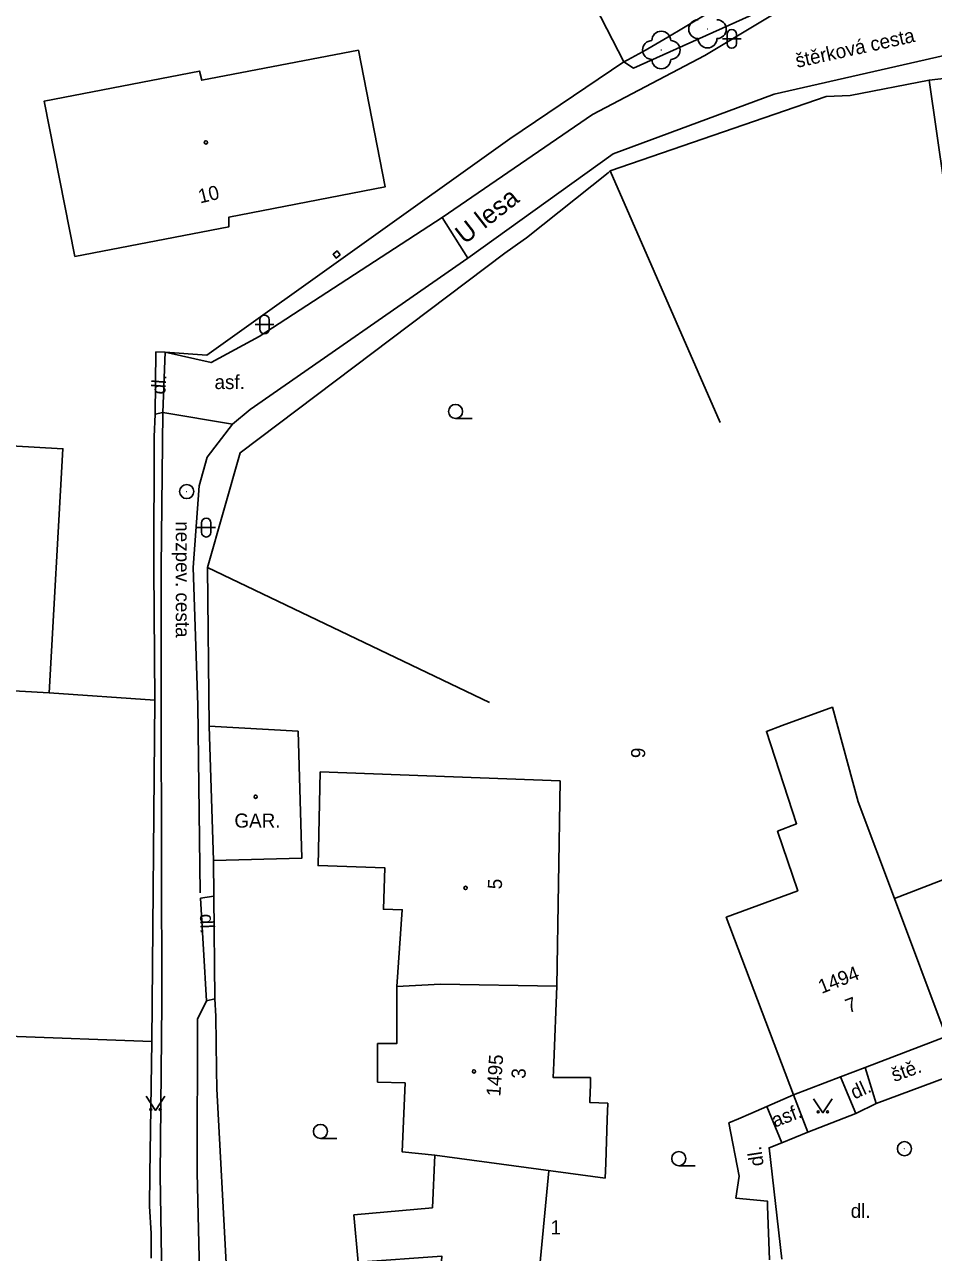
# Model space of a CAD drawing. Extents: x -584400 to -581602, y -1210894 to -1208793.
# Drawn here: x -583273.3 to -583224.9, y -1209541.9 to -1209476.6 of the extents above; entities that cross this region are included whole.
import ezdxf

# ---------------------------------------------------------------- set-up
doc = ezdxf.new("R2010")
doc.units = 0
for name, color, linetype in [('BUDOVY_MĚŘ', 7, 'Continuous'), ('BUDOVY_NEMĚŘ', 7, 'Continuous'), ('MAP_ZN_BP', 7, 'Continuous'), ('NÁZVY_ULIC_TOK_SMĚR', 7, 'Continuous'), ('OBVOD_PILÍŘE', 7, 'Continuous'), ('POMOC_POPIS', 7, 'Continuous'), ('ROZHRANÍ_PLOCH', 7, 'Continuous'), ('ZELEŇ', 7, 'Continuous'), ('ZN_BUDOV', 7, 'Continuous'), ('ZN_DOPLŇKOVÉ', 7, 'Continuous'), ('ZN_KULTUR', 7, 'Continuous'), ('Č_POPIS_EVID', 7, 'Continuous'), ('Č_POPIS_ORIENT', 7, 'Continuous')]:
    doc.layers.add(name, color=color, linetype=linetype)

msp = doc.modelspace()

# ---------------------------------------------------------------- linework, layer by layer
at = {"layer": 'BUDOVY_MĚŘ'}
for points in [[(-583270.59, -1209488.95), (-583262.4, -1209487.38), (-583262.39, -1209486.86), (-583254.08, -1209485.25), (-583255.49, -1209477.98)], [(-583225.12, -1209479.58), (-583224.33, -1209485.13), (-583221.4, -1209484.79), (-583222.19, -1209479.24), (-583225.12, -1209479.58)], [(-583281.65, -1209498.59), (-583271.23, -1209499.18), (-583271.96, -1209512.17), (-583282.38, -1209511.58), (-583281.65, -1209498.59)], [(-583258.7, -1209514.2), (-583263.44, -1209513.95), (-583263.22, -1209521.09), (-583258.52, -1209520.97), (-583258.7, -1209514.2)], [(-583244.76, -1209516.85), (-583257.54, -1209516.38)], [(-583251.14, -1209527.66), (-583253.46, -1209527.79)], [(-583242.36, -1209537.99), (-583242.33, -1209537.19), (-583242.26, -1209534.87), (-583242.23, -1209534), (-583243.18, -1209533.97), (-583243.18, -1209533.87), (-583243.15, -1209533.01), (-583243.15, -1209532.64), (-583244.78, -1209532.64), (-583245.13, -1209532.64), (-583245.1, -1209531.86), (-583244.94, -1209527.78), (-583251.14, -1209527.66)], [(-583254.48, -1209530.83), (-583253.46, -1209530.83), (-583253.46, -1209527.79)], [(-583251.55, -1209539.57), (-583251.44, -1209536.77), (-583253.18, -1209536.58), (-583253.02, -1209532.92), (-583254.48, -1209532.88), (-583254.48, -1209530.83)], [(-583232.34, -1209533.55), (-583229.85, -1209532.6), (-583228.53, -1209532.1), (-583224.22, -1209530.45)], [(-583242.36, -1209537.99), (-583251.44, -1209536.77)], [(-583255.74, -1209539.94), (-583251.55, -1209539.57)], [(-583251.98, -1209555.22), (-583251.06, -1209542.14), (-583255.52, -1209542.45), (-583255.74, -1209539.94)]]:
    msp.add_lwpolyline(points, dxfattribs=at)
at = {"layer": 'BUDOVY_NEMĚŘ'}
for points in [[(-583255.49, -1209477.98), (-583263.84, -1209479.58), (-583263.96, -1209479.09), (-583272.22, -1209480.69), (-583270.59, -1209488.95)], [(-583226.96, -1209523.11), (-583218.62, -1209519.89), (-583222.5, -1209508.4), (-583223.55, -1209501.49), (-583218.76, -1209500.73), (-583217.77, -1209507.6), (-583217.68, -1209509.16), (-583217.59, -1209510.64), (-583211.83, -1209525.68)], [(-583232.34, -1209533.55), (-583235.92, -1209524.11), (-583232.12, -1209522.7), (-583233.19, -1209519.53), (-583232.18, -1209519.13), (-583233.79, -1209514.22), (-583232.95, -1209513.91), (-583230.27, -1209512.94), (-583228.9, -1209517.96), (-583226.96, -1209523.11), (-583224.22, -1209530.45)], [(-583253.46, -1209527.79), (-583253.17, -1209523.71), (-583254.17, -1209523.68), (-583254.09, -1209521.48), (-583257.65, -1209521.36), (-583257.54, -1209516.38)], [(-583244.76, -1209516.85), (-583244.94, -1209527.78)], [(-583251.98, -1209555.22), (-583247.08, -1209555.68), (-583245.37, -1209537.59)]]:
    msp.add_lwpolyline(points, dxfattribs=at)
at = {"layer": 'MAP_ZN_BP'}
for centre, radius in [((-583264.64, -1209501.461), 0.375), ((-583264.64, -1209501.461), 0.0005), ((-583226.44, -1209536.421), 0.375), ((-583226.44, -1209536.421), 0.0005)]:
    msp.add_circle(centre, radius, dxfattribs=at)
at = {"layer": 'OBVOD_PILÍŘE'}
msp.add_lwpolyline([(-583256.47, -1209488.86), (-583256.64, -1209488.66), (-583256.85, -1209488.84), (-583256.68, -1209489.04), (-583256.47, -1209488.86)], dxfattribs=at)
at = {"layer": 'ROZHRANÍ_PLOCH'}
for points in [[(-583226.81, -1209472.03), (-583231.1, -1209474.67), (-583231.17, -1209474.5), (-583233.01, -1209475.41), (-583233.1, -1209475.23), (-583233.58, -1209475.47), (-583233.48, -1209475.62), (-583240.86, -1209478.94), (-583241.37, -1209478.6)], [(-583243.05, -1209481.4), (-583237.07, -1209478.27), (-583231.1, -1209474.67)], [(-583213.29, -1209477.22), (-583222.38, -1209477.82), (-583233.38, -1209480.32), (-583241.95, -1209483.5), (-583249.68, -1209489.04)], [(-583243.05, -1209481.4), (-583251.04, -1209486.89)], [(-583249.68, -1209489.04), (-583251.04, -1209486.89), (-583260.79, -1209493.22), (-583263.34, -1209494.6), (-583265.78, -1209494.05)], [(-583249.68, -1209489.04), (-583261.27, -1209497.1), (-583262.2, -1209497.88)], [(-583265.91, -1209497.25), (-583265.78, -1209494.05)], [(-583262.2, -1209497.88), (-583265.91, -1209497.25), (-583266.32, -1209497.34)], [(-583255.54, -1209578.93), (-583260.75, -1209564.34), (-583262.86, -1209558.55), (-583265.85, -1209549.98), (-583266.05, -1209537.82), (-583265.97, -1209528.68), (-583266, -1209513), (-583266, -1209505.5), (-583265.91, -1209497.25)], [(-583263.92, -1209522.8), (-583264.05, -1209512.82), (-583264.29, -1209505.5), (-583263.98, -1209501.16), (-583263.56, -1209499.64), (-583262.2, -1209497.88)], [(-583263.14, -1209528.44), (-583263.58, -1209528.56), (-583263.9, -1209523.1), (-583263.19, -1209522.99)], [(-583253.38, -1209578.02), (-583258.48, -1209563.89), (-583260.22, -1209558.54), (-583263.44, -1209550.06), (-583263.85, -1209547.51), (-583264.08, -1209537.68), (-583264.06, -1209529.53), (-583263.58, -1209528.56)], [(-583227.95, -1209534.01), (-583228.53, -1209532.1)], [(-583229.03, -1209534.54), (-583229.85, -1209532.6)], [(-583223.59, -1209532.4), (-583227.95, -1209534.01)], [(-583231.59, -1209535.55), (-583232.34, -1209533.55)], [(-583231.59, -1209535.54), (-583232.34, -1209533.55)], [(-583232.96, -1209536.1), (-583233.77, -1209534.18)], [(-583227.95, -1209534.01), (-583229.03, -1209534.54)], [(-583229.03, -1209534.54), (-583231.59, -1209535.55)], [(-583231.59, -1209535.55), (-583232.96, -1209536.1), (-583233.64, -1209536.37), (-583232.97, -1209542.3)]]:
    msp.add_lwpolyline(points, dxfattribs=at)
at = {"layer": 'ZELEŇ'}
for centre in [(-583236.92, -1209476.86), (-583239.38, -1209477.97)]:
    msp.add_circle(centre, 0.0005, dxfattribs=at)
for centre, start, end in [((-583237.42, -1209476.86), 89.99999, 269.99999), ((-583236.42, -1209476.86), 270, 89.99999), ((-583239.38, -1209477.47), 0, 179.99999), ((-583236.92, -1209477.36), 179.99999, 359.99999), ((-583239.88, -1209477.97), 89.99999, 269.99999), ((-583238.88, -1209477.97), 270, 89.99999), ((-583239.38, -1209478.47), 179.99999, 359.99999)]:
    msp.add_arc(centre, 0.5, start, end, dxfattribs=at)
at = {"layer": 'ZN_BUDOV'}
for centre in [(-583263.62, -1209482.89), (-583260.97, -1209517.7), (-583249.8, -1209522.55), (-583249.35, -1209532.31)]:
    msp.add_circle(centre, 0.0875, dxfattribs=at)
at = {"layer": 'ZN_DOPLŇKOVÉ'}
for points in [[(-583273.03, -1209474.41), (-583245.93, -1209469.74), (-583241.37, -1209478.6)], [(-583240.18, -1209477.96), (-583240.09, -1209477.91), (-583239.04, -1209477.29), (-583238.2, -1209476.79), (-583236.42, -1209475.73), (-583232.06, -1209473.15), (-583231.95, -1209473.09)], [(-583266.28, -1209494.02), (-583265.78, -1209494.05), (-583263.57, -1209494.2), (-583247.44, -1209482.7), (-583241.37, -1209478.6), (-583241.16, -1209478.49), (-583240.18, -1209477.96)], [(-583225.12, -1209479.58), (-583229.33, -1209480.39)], [(-583230.61, -1209480.45), (-583242.1, -1209484.4)], [(-583230.61, -1209480.45), (-583229.33, -1209480.39)], [(-583242.21, -1209484.5), (-583246.55, -1209487.96)], [(-583236.24, -1209497.79), (-583242.1, -1209484.4), (-583242.21, -1209484.5)], [(-583247.71, -1209488.78), (-583246.74, -1209488.09)], [(-583246.74, -1209488.09), (-583246.55, -1209487.96)], [(-583247.71, -1209488.78), (-583261.79, -1209499.4), (-583263.53, -1209505.5), (-583248.53, -1209512.69)], [(-583266.37, -1209498.55), (-583266.32, -1209497.34), (-583266.28, -1209494.02)], [(-583266.34, -1209512.56), (-583266.39, -1209505.56), (-583266.37, -1209498.55)], [(-583263.53, -1209505.5), (-583263.44, -1209513.95)], [(-583266.34, -1209512.56), (-583271.96, -1209512.17)], [(-583266.49, -1209530.72), (-583266.34, -1209512.56)], [(-583263.19, -1209522.99), (-583263.22, -1209521.09)], [(-583263.14, -1209528.44), (-583263.19, -1209522.99)], [(-583263.09, -1209529.37), (-583263.14, -1209528.44)], [(-583263.06, -1209532.2), (-583263.09, -1209529.37)], [(-583266.49, -1209530.72), (-583274.15, -1209530.43)], [(-583266.61, -1209537.79), (-583266.49, -1209530.72)], [(-583263.04, -1209533.23), (-583263.06, -1209532.2)], [(-583259.2, -1209558.01), (-583261.81, -1209550.54), (-583262.53, -1209542.85), (-583263.04, -1209533.23)], [(-583232.34, -1209533.55), (-583233.77, -1209534.18)], [(-583234.62, -1209534.55), (-583233.77, -1209534.18)], [(-583235.28, -1209534.83), (-583235.79, -1209535.05)], [(-583234.62, -1209534.55), (-583235.28, -1209534.83)], [(-583235.23, -1209537.89), (-583235.79, -1209535.05)], [(-583266.62, -1209539.48), (-583266.61, -1209537.79)], [(-583235.23, -1209537.89), (-583235.41, -1209539.05)], [(-583233.72, -1209539.47), (-583233.72, -1209539.22), (-583235.41, -1209539.05)], [(-583266.53, -1209540.93), (-583266.62, -1209539.48)], [(-583233.63, -1209542.33), (-583233.72, -1209539.47)], [(-583266.54, -1209542.24), (-583266.53, -1209540.93)]]:
    msp.add_lwpolyline(points, dxfattribs=at)
at = {"layer": 'ZN_KULTUR'}
for p, q in [((-583235.88, -1209477.63), (-583235.88, -1209477.13)), ((-583235.38, -1209477.63), (-583235.38, -1209477.13)), ((-583236.13, -1209477.38), (-583235.13, -1209477.38)), ((-583260.75, -1209492.82), (-583260.75, -1209492.32)), ((-583260.25, -1209492.82), (-583260.25, -1209492.32)), ((-583261, -1209492.57), (-583260, -1209492.57)), ((-583250.33, -1209497.575), (-583249.455, -1209497.575)), ((-583264.1, -1209503.38), (-583263.1, -1209503.38)), ((-583263.85, -1209503.63), (-583263.85, -1209503.13)), ((-583263.35, -1209503.63), (-583263.35, -1209503.13)), ((-583257.52, -1209535.875), (-583256.645, -1209535.875)), ((-583238.45, -1209537.325), (-583237.575, -1209537.325))]:
    msp.add_line(p, q, dxfattribs=at)
for points in [[(-583266.8, -1209533.63), (-583266.3, -1209534.38), (-583265.8, -1209533.63)], [(-583231.28, -1209533.76), (-583230.78, -1209534.51), (-583230.28, -1209533.76)]]:
    msp.add_lwpolyline(points, dxfattribs=at)
for centre, radius in [((-583250.33, -1209497.2), 0.375), ((-583266.55, -1209534.33), 0.05), ((-583266.05, -1209534.33), 0.05), ((-583231.03, -1209534.46), 0.05), ((-583230.53, -1209534.46), 0.05), ((-583257.52, -1209535.5), 0.375), ((-583238.45, -1209536.95), 0.375)]:
    msp.add_circle(centre, radius, dxfattribs=at)
for centre, start, end in [((-583235.63, -1209477.13), 0, 179.99999), ((-583235.63, -1209477.63), 179.99999, 359.99999), ((-583260.5, -1209492.32), 0, 179.99999), ((-583260.5, -1209492.82), 179.99999, 359.99999), ((-583263.6, -1209503.13), 0, 179.99999), ((-583263.6, -1209503.63), 179.99999, 359.99999)]:
    msp.add_arc(centre, 0.25, start, end, dxfattribs=at)

# ---------------------------------------------------------------- texts
at = {"layer": 'NÁZVY_ULIC_TOK_SMĚR'}
msp.add_text('U lesa', height=1, rotation=38.05001, dxfattribs=at).set_placement((-583249.85, -1209488.34))
at = {"layer": 'POMOC_POPIS'}
for s, rotation, p in [('štěrková cesta', 12.40179, (-583232.15, -1209478.92)), ('dl.', 85.86535, (-583265.79, -1209496.31)), ('nezpev. cesta', 270, (-583265.22, -1209503.04)), ('dl.', 272.16108, (-583263.94, -1209523.94)), ('ště.', 19.82245, (-583226.98, -1209532.88)), ('dl.', 24.39998, (-583229.1, -1209533.81)), ('asf.', 20.52999, (-583233.34, -1209535.3)), ('dl.', 98.66413, (-583233.92, -1209537.3))]:
    msp.add_text(s, height=0.75, rotation=rotation, dxfattribs=at).set_placement(p)
for s, p in [('asf.', (-583263.16, -1209496.01)), ('GAR.', (-583262.1, -1209519.34)), ('dl.', (-583229.3, -1209540.1))]:
    msp.add_text(s, height=0.75, dxfattribs=at).set_placement(p)
at = {"layer": 'Č_POPIS_EVID'}
for s, rotation, p in [('9', 87.72408, (-583240.25, -1209515.66)), ('7', 20.92631, (-583229.41, -1209529.22))]:
    msp.add_text(s, height=0.75, rotation=rotation, dxfattribs=at).set_placement(p)
msp.add_text('1', height=0.75, dxfattribs=at).set_placement((-583245.28, -1209540.98))
at = {"layer": 'Č_POPIS_ORIENT'}
for s, rotation, p in [('10', 13.57681, (-583263.93, -1209486.14)), ('5', 87.72001, (-583247.87, -1209522.63)), ('1494', 21.51027, (-583230.85, -1209528.19)), ('1495', 85.83756, (-583247.95, -1209533.66)), ('3', 87.72001, (-583246.61, -1209532.71))]:
    msp.add_text(s, height=0.75, rotation=rotation, dxfattribs=at).set_placement(p)

doc.saveas('drawing.dxf')
